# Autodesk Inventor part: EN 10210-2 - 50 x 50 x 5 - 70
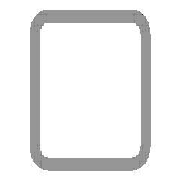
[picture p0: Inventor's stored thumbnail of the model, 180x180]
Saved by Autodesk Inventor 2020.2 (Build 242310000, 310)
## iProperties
IsCustomPart: 1
_CCFamilyMember: 16
_CCFamilyDisplayName: DIN EN 10210-2 (USAS B17.1 quadratisch) - Rohrleitung — In Klammern angegebene Größen wurden aufgehoben
_FrameMemberDoc: Frame Member File
_Version: 15.0.0
_GetPNFromCC: 1
Created: 2019-10
Part Number: EN 10210-2 - 50 x 50 x 5 - 70
Material: Stahl, weich
Description: Rohrleitung
Document SubType Name: Modeling
Standard: DIN
Designer: lutzd
Standard Revision: 2006-07
Standards Organization: DIN
Language: de-DE
Size Designation: 50 x 50 x 5
Categories: <MemberInstance><Categories><Category DisplayName="Profile" InternalName="089c4875-fa83-4c05-b084-43b9cc11f5ed" Mnemonic="GRDR"><CategoryParameter DisplayName="
Stock Number: 50 x 50 x 5
Mass: 479.81 g
Surface Area: 254.441 cm^2
Volume: 61.1222 cm^3
Density: 7.85 g/cm^3
Appearance: Semi-Polished(8)
G_L: 70,000 mm
G_W: 50,000 mm
G_H: 50,000 mm
Dimensions: 50x50x70 mm
Mass: 0,48 kg
DocNumber: ADSK-014293
Folder: .
+96DAD80D-4851-47E7-9DE4-68C94F0D3148+SCHNITTDETAIL1: Schnittwinkel 90,00 grd
VLT_Material: Stahl, weich
Title: Profil-Bauteil
Author: lutzd
Revision Number: -
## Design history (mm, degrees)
node "Startebene"
node "Endebene"
sketch "Skizze"
  geometry: L1 (-25, -17.5)-(-25, 17.5); L2 (-17.5, 25)-(17.5, 25); L3 (25, 17.5)-(25, -17.5); L4 (17.5, -25)-(-17.5, -25); L5 (-15, 20)-(15, 20); L6 (20, 15)-(20, -15); L7 (15, -20)-(-15, -20); L8 (-20, -15)-(-20, 15); L9 (0, 37.175)-(0, -37.175) reference; L10 (-37.175, 0)-(37.175, 0) reference; A1 r 7.5 centre (-17.5, -17.5) between (-25, -17.5) and (-17.5, -25); A2 r 7.5 centre (-17.5, 17.5) between (-17.5, 25) and (-25, 17.5); A3 r 7.5 centre (17.5, 17.5) between (25, 17.5) and (17.5, 25); A4 r 7.5 centre (17.5, -17.5) between (17.5, -25) and (25, -17.5); A5 r 5 centre (-15, -15) between (-20, -15) and (-15, -20); A6 r 5 centre (-15, 15) between (-15, 20) and (-20, 15); A7 r 5 centre (15, 15) between (20, 15) and (15, 20); A8 r 5 centre (15, -15) between (15, -20) and (20, -15)
  constraints: 16 end point, 16 point on circle, 16 tangent, 8 centre point, 6 equal radius, 4 parallel, 2 perpendicular, 2 other
  dimensions: "d7" = 7.5 radius of A1 (= G_IR); "d10" = 50 distance between parallel lines of L2 L4 (= G_H); "d11" = 50 distance between parallel lines of L1 L3 (= G_W); "d12" = 5 distance between parallel lines of L3 L6 (= G_T); "d15" = 25 distance between parallel lines of L2 L10 (= 0.5 x d10); "d16" = 25 distance between parallel lines of L9 L3 (= 0.5 x d11); "d19" = 5 radius of A5 (= G_T); "d20" = 5 distance between parallel lines of L4 L7 (= G_T)
extrude "Körper" new body sketch "Skizze" stored distance "d3" = 70 (= G_L); taper "d4" = 0 deg
node "Driven Length"
  sketch "Sketch3"
    geometry: L1 (0, 0)-(10, 0) reference
    constraints: 2 end point, 1 horizontal
  workplane "Work Plane3"
  sketch "Sketch4"
    geometry: L1 (-2, 25)-(12, 25) reference; L2 (-2, 95)-(12, 95) reference
    dimensions: "d18" = 70 distance between parallel lines of L1 L2 (derived)
workplane "Arbeitsebene4"
feature "Trennen1"
body "Solid1"
other parameters: "G_W" = 50 [user parameter; used in 1 equation term], "G_H" = 50 [user parameter; used in 1 equation term], "G_T" = 5 [user parameter; used in 3 equation terms], "G_IR" = 7.5 [user parameter; used in 1 equation term], "G_L" = 70 (= d18) [user parameter; used in 1 equation term], "G_OFFSET_START" = -25 [user parameter; used in 1 equation term], "G_OFFSET_END" = 0 [user parameter; used in 1 equation term], "d13" = 25 (= -G_OFFSET_START), "d14" = 95 (= G_OFFSET_END + B_L), "B_L" = 95 [user parameter; used in 1 equation term], "d17" = 90 deg
